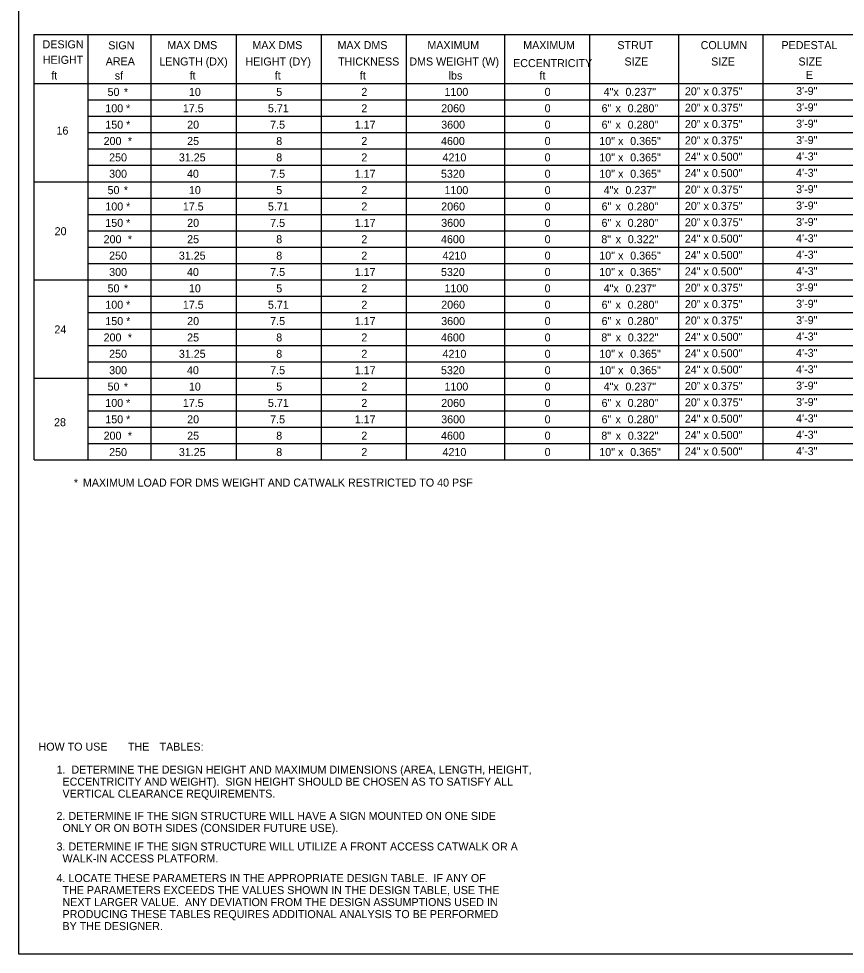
# Model space of a CAD drawing. Extents: x 3829340 to 3831660, y 499389 to 501171.
# Drawn here: x 3830221 to 3830530.9, y 500592.2 to 500942.8 of the extents above; entities that cross this region are included whole.
import ezdxf

# ---------------------------------------------------------------- set-up
doc = ezdxf.new("R2010")
doc.units = 0
for name, color, linetype in [('1', 7, 'Continuous'), ('2', 7, 'Continuous'), ('TABULATION', 7, 'Continuous')]:
    doc.layers.add(name, color=color, linetype=linetype)

msp = doc.modelspace()

# ---------------------------------------------------------------- linework, layer by layer
at = {"layer": '2'}
for p, q in [((3830220.96, 500592.19), (3830220.96, 501156.19)), ((3831006.96, 500592.19), (3830220.96, 500592.19))]:
    msp.add_line(p, q, dxfattribs=at)
at = {"layer": 'TABULATION'}
for p, q in [((3830226.8, 500936.98), (3830617.54, 500936.98)), ((3830226.8, 500777.46), (3830226.8, 500936.98)), ((3830247.05, 500777.46), (3830247.05, 500936.98)), ((3830270.67, 500777.46), (3830270.67, 500936.98)), ((3830302.57, 500777.46), (3830302.57, 500936.98)), ((3830334.48, 500777.46), (3830334.48, 500936.98)), ((3830366.38, 500777.46), (3830366.38, 500936.98)), ((3830403.2, 500777.46), (3830403.2, 500936.98)), ((3830435.1, 500777.46), (3830435.1, 500936.98)), ((3830468.54, 500777.46), (3830468.54, 500936.98)), ((3830500.07, 500777.46), (3830500.07, 500936.98)), ((3830226.8, 500918.58), (3830710.49, 500918.58)), ((3830247.05, 500912.44), (3830853.14, 500912.44)), ((3830247.05, 500906.3), (3830853.14, 500906.3)), ((3830247.05, 500900.17), (3830853.14, 500900.17)), ((3830247.05, 500894.03), (3830853.14, 500894.03)), ((3830247.05, 500887.9), (3830853.14, 500887.9)), ((3830226.8, 500881.76), (3830853.14, 500881.76)), ((3830247.05, 500875.63), (3830853.14, 500875.63)), ((3830247.05, 500869.49), (3830853.14, 500869.49)), ((3830247.05, 500863.36), (3830853.14, 500863.36)), ((3830247.05, 500857.22), (3830853.14, 500857.22)), ((3830247.05, 500851.08), (3830853.14, 500851.08)), ((3830226.8, 500844.95), (3830853.14, 500844.95)), ((3830247.05, 500838.81), (3830853.14, 500838.81)), ((3830247.05, 500832.68), (3830853.14, 500832.68)), ((3830247.05, 500826.54), (3830853.14, 500826.54)), ((3830247.05, 500820.41), (3830853.14, 500820.41)), ((3830247.05, 500814.27), (3830853.14, 500814.27)), ((3830226.8, 500808.14), (3830853.14, 500808.14)), ((3830247.05, 500802), (3830853.14, 500802)), ((3830247.05, 500795.86), (3830853.14, 500795.86)), ((3830247.05, 500789.73), (3830853.14, 500789.73)), ((3830247.05, 500783.59), (3830853.14, 500783.59)), ((3830226.8, 500777.46), (3830853.14, 500777.46))]:
    msp.add_line(p, q, dxfattribs=at)

# ---------------------------------------------------------------- texts
at = {"layer": '1'}
for s, height, p in [('HOW TO USE', 3, (3830228.4, 500668.5)), (' THE', 3, (3830260.81, 500668.5)), (' TABLES:', 3, (3830272.66, 500668.5)), ('1.  DETERMINE THE DESIGN HEIGHT AND MAXIMUM DIMENSIONS (AREA, LENGTH, HEIGHT, ', 2.9999, (3830235.15, 500659.9)), ('  ECCENTRICITY AND WEIGHT).  SIGN HEIGHT SHOULD BE CHOSEN AS TO SATISFY ALL', 2.9999, (3830235.15, 500655.4)), ('  VERTICAL CLEARANCE REQUIREMENTS.', 2.9999, (3830235.15, 500650.9)), ('2. DETERMINE IF THE SIGN STRUCTURE WILL HAVE A SIGN MOUNTED ON ONE SIDE', 2.9999, (3830235.15, 500642.55)), ('  ONLY OR ON BOTH SIDES (CONSIDER FUTURE USE).', 2.9999, (3830235.15, 500638.05)), ('3. DETERMINE IF THE SIGN STRUCTURE WILL UTILIZE A FRONT ACCESS CATWALK OR A', 2.9999, (3830235.15, 500631.09)), ('  WALK-IN ACCESS PLATFORM.', 2.9999, (3830235.15, 500626.59)), ('4. LOCATE THESE PARAMETERS IN THE APPROPRIATE DESIGN TABLE.  IF ANY OF', 2.9999, (3830235.15, 500619.25)), ('  THE PARAMETERS EXCEEDS THE VALUES SHOWN IN THE DESIGN TABLE, USE THE', 2.9999, (3830235.15, 500614.75)), ('  NEXT LARGER VALUE.  ANY DEVIATION FROM THE DESIGN ASSUMPTIONS USED IN', 2.9999, (3830235.15, 500610.25)), ('  PRODUCING THESE TABLES REQUIRES ADDITIONAL ANALYSIS TO BE PERFORMED', 2.9999, (3830235.15, 500605.75)), ('  BY THE DESIGNER.', 2.9999, (3830235.15, 500601.25))]:
    msp.add_text(s, height=height, dxfattribs=at).set_placement(p)
at = {"layer": 'TABULATION'}
for s, height, p in [('DESIGN', 3, (3830229.91, 500931.75)), ('SIGN', 3, (3830254.54, 500931.39)), ('MAX DMS', 3, (3830276.68, 500931.45)), ('MAX DMS', 3, (3830308.59, 500931.45)), ('MAX DMS', 3, (3830340.49, 500931.45)), ('MAXIMUM ', 3, (3830374.2, 500931.45)), ('MAXIMUM', 3, (3830410.13, 500931.45)), ('STRUT', 3, (3830445.43, 500931.45)), ('COLUMN', 3, (3830476.67, 500931.45)), ('PEDESTAL', 3, (3830506.96, 500931.45)), ('HEIGHT', 3, (3830230, 500925.94)), ('AREA', 3, (3830253.6, 500925.39)), ('LENGTH (DX)', 2.9996, (3830273.69, 500925.31)), ('HEIGHT (DY)', 2.9996, (3830306.02, 500925.31)), ('THICKNESS', 3, (3830340.71, 500925.31)), ('DMS WEIGHT (W)', 2.9996, (3830367.43, 500925.31)), ('ECCENTRICITY', 2.9996, (3830406.34, 500924.71)), ('SIZE', 3, (3830448.11, 500925.31)), ('SIZE', 3, (3830480.6, 500925.31)), ('SIZE', 3, (3830513.33, 500925.31)), ('ft', 3, (3830233.18, 500920.05)), ('sf', 3, (3830257, 500920.05)), ('ft', 3, (3830285.05, 500920.05)), ('ft', 3, (3830316.96, 500920.05)), ('ft', 3, (3830348.86, 500920.05)), ('lbs', 3, (3830382.17, 500920.05)), ('ft', 3, (3830416.22, 500920.05)), ('E', 3, (3830516.13, 500920.3)), ('50', 3, (3830254.29, 500913.92)), (' *', 3, (3830259.27, 500913.92)), ('10', 3, (3830284.78, 500913.92)), ('5', 3, (3830317.52, 500913.92)), ('2', 3, (3830349.43, 500913.92)), ('1100', 3, (3830380.61, 500913.92)), ('0', 3, (3830418.16, 500913.92)), ('4"x', 3, (3830440.29, 500913.92)), (' 0.237"', 3, (3830447.35, 500913.92)), ('20" x 0.375"', 2.9996, (3830470.75, 500914.14)), ('3\'-9"', 3, (3830512.45, 500914.28)), ('100', 3, (3830253.45, 500907.78)), (' *', 3, (3830260.11, 500907.78)), ('17.5', 3, (3830282.5, 500907.78)), ('5.71', 3, (3830314.41, 500907.78)), ('2', 3, (3830349.43, 500907.78)), ('2060', 3, (3830379.38, 500907.78)), ('0', 3, (3830418.16, 500907.78)), ('6"', 3, (3830439.51, 500907.78)), (' x', 3, (3830443.62, 500907.78)), (' 0.280"', 3, (3830448.17, 500907.78)), ('20" x 0.375"', 2.9996, (3830470.75, 500908.01)), ('3\'-9"', 3, (3830512.45, 500908.14)), ('16', 3, (3830235.14, 500899.41)), ('150', 3, (3830253.44, 500901.64)), (' *', 3, (3830260.12, 500901.64)), ('20', 3, (3830284.13, 500901.64)), ('7.5', 3, (3830315.26, 500901.64)), ('1.17', 3, (3830346.96, 500901.64)), ('3600', 3, (3830379.38, 500901.64)), ('0', 3, (3830418.16, 500901.64)), ('6"', 3, (3830439.51, 500901.64)), (' x', 3, (3830443.62, 500901.64)), (' 0.280"', 3, (3830448.17, 500901.64)), ('20" x 0.375"', 2.9996, (3830470.75, 500901.87)), ('3\'-9"', 3, (3830512.45, 500902.01)), ('200', 3, (3830252.8, 500895.51)), (' *', 3, (3830260.76, 500895.51)), ('25', 3, (3830284.12, 500895.51)), ('8', 3, (3830317.52, 500895.51)), ('2', 3, (3830349.43, 500895.51)), ('4600', 3, (3830379.31, 500895.51)), ('0', 3, (3830418.16, 500895.51)), ('10"', 3, (3830438.66, 500895.51)), (' 0.365"', 3, (3830449.14, 500895.51)), ('20" x 0.375"', 2.9996, (3830470.75, 500895.74)), ('3\'-9"', 3, (3830512.45, 500895.87)), (' x', 3, (3830444.58, 500895.51)), ('250', 3, (3830254.87, 500889.37)), ('31.25', 3, (3830281.01, 500889.37)), ('8', 3, (3830317.52, 500889.37)), ('2', 3, (3830349.43, 500889.37)), ('4210', 3, (3830379.88, 500889.37)), ('0', 3, (3830418.16, 500889.37)), ('10"', 3, (3830438.66, 500889.37)), (' x', 3, (3830444.58, 500889.37)), (' 0.365"', 3, (3830449.14, 500889.37)), ('24" x 0.500"', 2.9996, (3830470.71, 500889.6)), ('4\'-3"', 3, (3830512.45, 500889.73)), ('300', 3, (3830254.88, 500883.24)), ('40', 3, (3830284.06, 500883.24)), ('7.5', 3, (3830315.26, 500883.24)), ('1.17', 3, (3830346.96, 500883.24)), ('5320', 3, (3830379.3, 500883.24)), ('0', 3, (3830418.16, 500883.24)), ('10"', 3, (3830438.66, 500883.24)), (' x', 3, (3830444.58, 500883.24)), (' 0.365"', 3, (3830449.14, 500883.24)), ('24" x 0.500"', 2.9996, (3830470.71, 500883.47)), ('4\'-3"', 3, (3830512.45, 500883.6)), ('50', 3, (3830254.29, 500877.1)), (' *', 3, (3830259.27, 500877.1)), ('10', 3, (3830284.78, 500877.1)), ('5', 3, (3830317.52, 500877.1)), ('2', 3, (3830349.43, 500877.1)), ('1100', 3, (3830380.61, 500877.1)), ('0', 3, (3830418.16, 500877.1)), ('4"x', 3, (3830440.29, 500877.1)), (' 0.237"', 3, (3830447.35, 500877.1)), ('20" x 0.375"', 2.9996, (3830470.75, 500877.33)), ('3\'-9"', 3, (3830512.45, 500877.46)), ('100', 3, (3830253.45, 500870.97)), (' *', 3, (3830260.11, 500870.97)), ('17.5', 3, (3830282.5, 500870.97)), ('5.71', 3, (3830314.41, 500870.97)), ('2', 3, (3830349.43, 500870.97)), ('2060', 3, (3830379.38, 500870.97)), ('0', 3, (3830418.16, 500870.97)), ('6"', 3, (3830439.51, 500870.97)), (' 0.280"', 3, (3830448.17, 500870.97)), ('20" x 0.375"', 2.9996, (3830470.75, 500871.19)), ('3\'-9"', 3, (3830512.45, 500871.33)), (' x', 3, (3830443.62, 500870.97)), ('150', 3, (3830253.44, 500864.83)), (' *', 3, (3830260.12, 500864.83)), ('20', 3, (3830284.13, 500864.83)), ('7.5', 3, (3830315.26, 500864.83)), ('1.17', 3, (3830346.96, 500864.83)), ('3600', 3, (3830379.38, 500864.83)), ('0', 3, (3830418.16, 500864.83)), ('6"', 3, (3830439.51, 500864.83)), (' x', 3, (3830443.62, 500864.83)), (' 0.280"', 3, (3830448.17, 500864.83)), ('20" x 0.375"', 2.9996, (3830470.75, 500865.06)), ('3\'-9"', 3, (3830512.45, 500865.19)), ('20', 3, (3830234.43, 500861.7)), ('200', 3, (3830252.8, 500858.7)), (' *', 3, (3830260.76, 500858.7)), ('25', 3, (3830284.12, 500858.7)), ('8', 3, (3830317.52, 500858.7)), ('2', 3, (3830349.43, 500858.7)), ('4600', 3, (3830379.31, 500858.7)), ('0', 3, (3830418.16, 500858.7)), ('8"', 3, (3830439.42, 500858.7)), (' x', 3, (3830443.68, 500858.7)), (' 0.322"', 3, (3830448.23, 500858.7)), ('24" x 0.500"', 2.9996, (3830470.71, 500858.92)), ('4\'-3"', 3, (3830512.45, 500859.06)), ('250', 3, (3830254.87, 500852.56)), ('31.25', 3, (3830281.01, 500852.56)), ('8', 3, (3830317.52, 500852.56)), ('2', 3, (3830349.43, 500852.56)), ('4210', 3, (3830379.88, 500852.56)), ('0', 3, (3830418.16, 500852.56)), ('10"', 3, (3830438.66, 500852.56)), (' x', 3, (3830444.58, 500852.56)), (' 0.365"', 3, (3830449.14, 500852.56)), ('24" x 0.500"', 2.9996, (3830470.71, 500852.79)), ('4\'-3"', 3, (3830512.45, 500852.92)), ('300', 3, (3830254.88, 500846.42)), ('40', 3, (3830284.06, 500846.42)), ('7.5', 3, (3830315.26, 500846.42)), ('1.17', 3, (3830346.96, 500846.42)), ('5320', 3, (3830379.3, 500846.42)), ('0', 3, (3830418.16, 500846.42)), ('10"', 3, (3830438.66, 500846.42)), (' 0.365"', 3, (3830449.14, 500846.42)), ('24" x 0.500"', 2.9996, (3830470.71, 500846.65)), ('4\'-3"', 3, (3830512.45, 500846.78)), (' x', 3, (3830444.58, 500846.42)), ('50', 3, (3830254.29, 500840.29)), (' *', 3, (3830259.27, 500840.29)), ('10', 3, (3830284.78, 500840.29)), ('5', 3, (3830317.52, 500840.29)), ('2', 3, (3830349.43, 500840.29)), ('1100', 3, (3830380.61, 500840.29)), ('0', 3, (3830418.16, 500840.29)), ('4"x', 3, (3830440.29, 500840.29)), (' 0.237"', 3, (3830447.35, 500840.29)), ('20" x 0.375"', 2.9996, (3830470.75, 500840.52)), ('3\'-9"', 3, (3830512.45, 500840.65)), ('100', 3, (3830253.45, 500834.15)), (' *', 3, (3830260.11, 500834.15)), ('17.5', 3, (3830282.5, 500834.15)), ('5.71', 3, (3830314.41, 500834.15)), ('2', 3, (3830349.43, 500834.15)), ('2060', 3, (3830379.38, 500834.15)), ('0', 3, (3830418.16, 500834.15)), ('6"', 3, (3830439.51, 500834.15)), (' x', 3, (3830443.62, 500834.15)), (' 0.280"', 3, (3830448.17, 500834.15)), ('20" x 0.375"', 2.9996, (3830470.75, 500834.38)), ('3\'-9"', 3, (3830512.45, 500834.51)), ('150', 3, (3830253.44, 500828.02)), (' *', 3, (3830260.12, 500828.02)), ('20', 3, (3830284.13, 500828.02)), ('7.5', 3, (3830315.26, 500828.02)), ('1.17', 3, (3830346.96, 500828.02)), ('3600', 3, (3830379.38, 500828.02)), ('0', 3, (3830418.16, 500828.02)), ('6"', 3, (3830439.51, 500828.02)), (' x', 3, (3830443.62, 500828.02)), (' 0.280"', 3, (3830448.17, 500828.02)), ('20" x 0.375"', 2.9996, (3830470.75, 500828.25)), ('3\'-9"', 3, (3830512.45, 500828.38)), ('24', 3, (3830234.35, 500824.89)), ('200', 3, (3830252.8, 500821.88)), (' *', 3, (3830260.76, 500821.88)), ('25', 3, (3830284.12, 500821.88)), ('8', 3, (3830317.52, 500821.88)), ('2', 3, (3830349.43, 500821.88)), ('4600', 3, (3830379.31, 500821.88)), ('0', 3, (3830418.16, 500821.88)), ('8"', 3, (3830439.42, 500821.88)), (' 0.322"', 3, (3830448.23, 500821.88)), ('24" x 0.500"', 2.9996, (3830470.71, 500822.11)), ('4\'-3"', 3, (3830512.45, 500822.24)), (' x', 3, (3830443.68, 500821.88)), ('250', 3, (3830254.87, 500815.75)), ('31.25', 3, (3830281.01, 500815.75)), ('8', 3, (3830317.52, 500815.75)), ('2', 3, (3830349.43, 500815.75)), ('4210', 3, (3830379.88, 500815.75)), ('0', 3, (3830418.16, 500815.75)), ('10"', 3, (3830438.66, 500815.75)), (' x', 3, (3830444.58, 500815.75)), (' 0.365"', 3, (3830449.14, 500815.75)), ('24" x 0.500"', 2.9996, (3830470.71, 500815.97)), ('4\'-3"', 3, (3830512.45, 500816.11)), ('300', 3, (3830254.88, 500809.61)), ('40', 3, (3830284.06, 500809.61)), ('7.5', 3, (3830315.26, 500809.61)), ('1.17', 3, (3830346.96, 500809.61)), ('5320', 3, (3830379.3, 500809.61)), ('0', 3, (3830418.16, 500809.61)), ('10"', 3, (3830438.66, 500809.61)), (' x', 3, (3830444.58, 500809.61)), (' 0.365"', 3, (3830449.14, 500809.61)), ('24" x 0.500"', 2.9996, (3830470.71, 500809.84)), ('4\'-3"', 3, (3830512.45, 500809.97)), ('50', 3, (3830254.29, 500803.47)), (' *', 3, (3830259.27, 500803.47)), ('10', 3, (3830284.78, 500803.47)), ('5', 3, (3830317.52, 500803.47)), ('2', 3, (3830349.43, 500803.47)), ('1100', 3, (3830380.61, 500803.47)), ('0', 3, (3830418.16, 500803.47)), ('4"x', 3, (3830440.29, 500803.47)), (' 0.237"', 3, (3830447.35, 500803.47)), ('20" x 0.375"', 2.9996, (3830470.75, 500803.7)), ('3\'-9"', 3, (3830512.45, 500803.84)), ('100', 3, (3830253.45, 500797.34)), (' *', 3, (3830260.11, 500797.34)), ('17.5', 3, (3830282.5, 500797.34)), ('5.71', 3, (3830314.41, 500797.34)), ('2', 3, (3830349.43, 500797.34)), ('2060', 3, (3830379.38, 500797.34)), ('0', 3, (3830418.16, 500797.34)), ('6"', 3, (3830439.51, 500797.34)), (' 0.280"', 3, (3830448.17, 500797.34)), ('20" x 0.375"', 2.9996, (3830470.75, 500797.57)), ('3\'-9"', 3, (3830512.45, 500797.7)), (' x', 3, (3830443.62, 500797.34)), ('28', 3, (3830234.21, 500790.11)), ('150', 3, (3830253.44, 500791.2)), (' *', 3, (3830260.12, 500791.2)), ('20', 3, (3830284.13, 500791.2)), ('7.5', 3, (3830315.26, 500791.2)), ('1.17', 3, (3830346.96, 500791.2)), ('3600', 3, (3830379.38, 500791.2)), ('0', 3, (3830418.16, 500791.2)), ('6"', 3, (3830439.51, 500791.2)), (' x', 3, (3830443.62, 500791.2)), (' 0.280"', 3, (3830448.17, 500791.2)), ('24" x 0.500"', 2.9996, (3830470.71, 500791.43)), ('4\'-3"', 3, (3830512.45, 500791.56)), ('200', 3, (3830252.8, 500785.07)), (' *', 3, (3830260.76, 500785.07)), ('25', 3, (3830284.12, 500785.07)), ('8', 3, (3830317.52, 500785.07)), ('2', 3, (3830349.43, 500785.07)), ('4600', 3, (3830379.31, 500785.07)), ('0', 3, (3830418.16, 500785.07)), ('8"', 3, (3830439.42, 500785.07)), (' x', 3, (3830443.68, 500785.07)), (' 0.322"', 3, (3830448.23, 500785.07)), ('24" x 0.500"', 2.9996, (3830470.71, 500785.3)), ('4\'-3"', 3, (3830512.45, 500785.43)), ('250', 3, (3830254.87, 500778.93)), ('31.25', 3, (3830281.01, 500778.93)), ('8', 3, (3830317.52, 500778.93)), ('2', 3, (3830349.43, 500778.93)), ('4210', 3, (3830379.88, 500778.93)), ('0', 3, (3830418.16, 500778.93)), ('10"', 3, (3830438.66, 500778.93)), (' x', 3, (3830444.58, 500778.93)), (' 0.365"', 3, (3830449.14, 500778.93)), ('24" x 0.500"', 2.9996, (3830470.71, 500779.16)), ('4\'-3"', 3, (3830512.45, 500779.29)), ('*', 3, (3830241.65, 500767.48)), (' MAXIMUM LOAD FOR DMS WEIGHT AND CATWALK RESTRICTED TO 40 PSF', 2.9996, (3830243.92, 500767.48))]:
    msp.add_text(s, height=height, dxfattribs=at).set_placement(p)

doc.saveas('drawing.dxf')
